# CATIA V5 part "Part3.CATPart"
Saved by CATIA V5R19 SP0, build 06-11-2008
Part number: Part1.3
Bounding box of the stored display mesh (mm): x -60.732 to 30, y -585.613 to 164.387, z -9.263 to 50.735
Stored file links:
  D:\thinkmotion-MPB\Dropbox\CIAO82010_JCF\BELAZOUZ\548-belazouz\Part3.CATPart
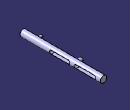
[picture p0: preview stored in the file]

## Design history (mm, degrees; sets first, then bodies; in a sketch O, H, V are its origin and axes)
Body1 (main body)
  Sketch1 on yz-plane, origin (0, 0, 0), H (0, 1, 0), V (0, 0, 1)
    line L1 (164.3871, 20.7358) -> (-585.6129, 20.7358)
    line L2 (164.3871, 20.7358) -> (164.3871, -9.2642)
    line L3 (164.3871, -9.2642) -> (-585.6129, -9.2642)
    line L4 (-585.6129, -9.2642) -> (-585.6129, 20.7358)
    length L1 = 750
    length L2 = 30
    horizontal: L1 H, L3 H
    vertical: L2 V, L4 V
  Shaft1: profile Sketch1, axis Sketch1.L1, angle 360
  Sketch2 on yz-plane, origin (0, 0, 0), H (0, 1, 0), V (0, 0, 1)
    construction line L1 (-66.6399, 19.9697) -> (107.015, 19.9697)
    line L2 (-66.6399, 35.7358) -> (107.015, 35.7358)
    line L3 (107.015, 4.2036) -> (-66.6399, 4.2036)
    arc A1 centre (107.015, 19.9697) radius 15.7661 from (107.015, 35.7358) to (107.015, 4.2036) cw
    arc A2 centre (-66.6399, 19.9697) radius 15.7661 from (-66.6399, 4.2036) to (-66.6399, 35.7358) cw
    reference projected line E1 through (0, 20.7358) direction (-1, 0) from axis of face of Shaft1 from Sketch1.L3
    distance L1 L2 = 15.7661
    distance L2 E1 = 15
    horizontal: L1 H
    tangency: A1 L2, A2 L2, A1 L3, A2 L3
  Pocket1: profile Sketch2, direction (1, 0, 0), length 30, opposite side length 36
  Sketch3 on yz-plane, origin (0, 0, 0), H (0, 1, 0), V (0, 0, 1)
    circle A1 centre (-471.3051, 22.2609) radius 10
    radius A1 = 10
  Pad1: profile Sketch3, direction (-1, 0, 0), length 60
  Sketch4 on yz-plane, origin (0, 0, 0), H (0, 1, 0), V (0, 0, 1)
    point P1 (-18.8197, 0)
    circle A1 centre (-101.2513, 19.372) radius 15.766
    radius A1 = 15.766
    coincidence: P1 H
  Pad2: profile Sketch4, direction (-1, 0, 0), length 60.732
  Sketch5 on yz-plane, origin (0, 0, 0), H (0, 1, 0), V (0, 0, 1)
    construction line L1 (-136.2017, 20.4336) -> (-296.6255, 20.4336)
    line L2 (-136.2017, 4.6676) -> (-296.6255, 4.6676)
    line L3 (-296.6255, 36.1996) -> (-136.2017, 36.1996)
    arc A1 centre (-296.6255, 20.4336) radius 15.766 from (-296.6255, 4.6676) to (-296.6255, 36.1996) cw
    arc A2 centre (-136.2017, 20.4336) radius 15.766 from (-136.2017, 36.1996) to (-136.2017, 4.6676) cw
    distance L3 L2 = 31.532
    tangency: A1 L2, A2 L2, A1 L3, A2 L3
  Pocket2: profile Sketch5, direction (-1, 0, 0), through (limit type 3), opposite side through (limit type 3)
  Point1: type OnSurface, Support end face of Pad2, Length 0, Direction (0.7445, -0.5316, -0.4039)
  DatumSurface1
  DatumSurface2
  DatumCurve1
